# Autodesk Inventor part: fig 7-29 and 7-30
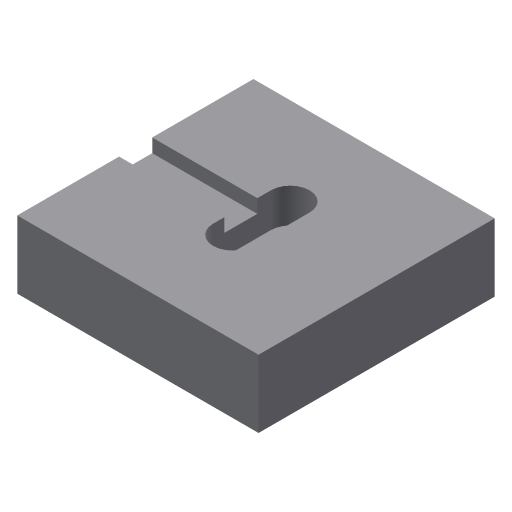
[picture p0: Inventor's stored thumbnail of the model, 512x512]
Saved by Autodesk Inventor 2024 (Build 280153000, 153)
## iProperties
Created: 2004-05
Part Number: fig 7-29 and 7-30
Document SubType Name: Modeling
Designer: CADCIM Technologies
Manufacturer: Standard
Standards Organization: Custom
Density: 1 g/cm^3
Material: Generic
Appearance: Default
Author: CADCIM Technologies
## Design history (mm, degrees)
sketch "Sketch1"
  geometry: L1 (-30.233, -25.517)-(22.302, -25.517); L2 (22.302, -25.517)-(22.302, 25.904); L3 (22.302, 25.904)-(-30.233, 25.904); L4 (-30.233, 25.904)-(-30.233, -25.517)
  constraints: 8 end point, 2 parallel, 1 horizontal, 1 perpendicular
extrude "Extrusion1" new body sketch "Sketch1" distance "d0" = 14.75; taper "d1" = 0 deg
sketch "Sketch2"
  geometry: L1 (1.047, -5.75)-(1.047, 6.846); L2 (-7.35, 6.845)-(-7.35, -5.75); A1 r 4.198 centre (-3.152, 6.846) between (1.047, 6.846) and (-7.35, 6.845); A2 r 4.198 centre (-3.152, -5.75) between (-7.35, -5.75) and (1.047, -5.75)
  constraints: 4 end point, 4 point on circle, 4 tangent, 2 centre point, 1 parallel
extrude "Extrusion2" cut sketch "Sketch2" distance "d2" = 7.5; taper "d3" = 0 deg
sketch "Sketch3"
  geometry: L1 (-7.5, 0)-(-7.5, 12.595) reference; L2 (-7.5, 0)-(0, 0) reference; L3 (-7.5, 2.416)-(-4.537, 2.416); L4 (-4.537, 2.416)-(-4.537, 9.616); L5 (-4.537, 9.616)-(-7.5, 9.616)
  constraints: 6 end point, 2 perpendicular, 2 point on line, 1 parallel
extrude "Extrusion3" cut sketch "Sketch3" extent not by distance; stored distance "d4" = 6.75; taper "d5" = 0 deg
body "Solid1"
